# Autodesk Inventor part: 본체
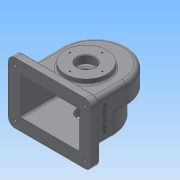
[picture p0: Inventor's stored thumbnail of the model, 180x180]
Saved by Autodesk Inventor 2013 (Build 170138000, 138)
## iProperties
Created: 2017-11
Part Number: 본체
Material: 일반
Document SubType Name: Modeling
Designer: Administrator
Density: 1 g/cm^3
Author: Administrator
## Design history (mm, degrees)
sketch "스케치1"
  geometry: L1 (-58, 0)-(-58, -80); L2 (58, 0)-(58, -80); L3 (-58, -80)-(58, -80); A1 r 58 centre (0, 0) between (58, 0) and (-58, 0); 1 further point
  constraints: 6 end point, 2 parallel, 2 point on circle, 2 tangent, 1 centre point, 1 coincident, 1 perpendicular, 1 vertical
  dimensions: "d0" = 116 diameter of A1; "d2" = 80 vertical distance of L2.end point (0, 0)
extrude "돌출1" new body sketch "스케치1" stored distance "d3" = 38; taper "d4" = 0 deg
sketch "스케치6"
  geometry: L1 (-58, -80)-(58, -80) reference; L2 (-75, -65)-(75, -65); L3 (75, -65)-(75, -80); L4 (75, -80)-(-75, -80); L5 (-75, -80)-(-75, -65); 1 further point
  constraints: 8 end point, 2 midpoint, 2 parallel, 1 horizontal, 1 perpendicular, 1 point on line
  dimensions: "d8" = 15 distance between parallel lines of L1 L2; "d9" = 150 distance between parallel lines of L3 L5
sketch "스케치7"
  geometry: L1 (58, -80)-(58, 0) reference; L2 (-58, 0)-(-58, -80) reference; L3 (-58, -80)-(58, -80) reference; L4 (-58, -23)-(-58, -80); L5 (58, -23)-(58, -80); L6 (-58, -80)-(58, -80); A1 r 58 centre (0, -23) between (58, -23) and (-58, -23); 4 further points
  constraints: 8 end point, 2 point on circle, 2 point on line, 2 tangent, 1 centre point, 1 collinear
  dimensions: "d12" = 116 diameter of A1; "d13" = 57 distance from line of L3 A1.centre; "d14" = 58 distance from line of L2 A1.centre
extrude "돌출3" join sketch "스케치7" distance "d15" = 38; taper "d16" = 0 deg
feature "쉘2" dims "d17" = 5
extrude "돌출4" join sketch "스케치6" stored distance "d18" = 110; taper "d19" = 0 deg
sketch "스케치9"
  geometry: L1 (0, 0)-(0, 110) reference; L2 (150, 0)-(0, 0) reference; L3 (150, 0)-(150, 110) reference; L4 (22, 88)-(128, 88); L5 (128, 88)-(128, 22); L6 (128, 22)-(22, 22); L7 (22, 22)-(22, 88); 1 further point
  constraints: 8 end point, 2 parallel, 1 horizontal, 1 perpendicular
  dimensions: "d24" = 66 distance between parallel lines of L6 L4; "d27" = 22 distance between parallel lines of L3 L5; "d28" = 22 distance between parallel lines of L2 L6; "d29" = 22 distance between parallel lines of L1 L7
extrude "돌출5" cut sketch "스케치9" distance "d30" = 15; taper "d31" = 0 deg
sketch "스케치10"
  geometry: L1 (-58, 0)-(-58, -65) reference; L2 (-67.459, -15)-(82.264, -15); L3 (-75, -80)-(75, -80) reference; C1 r 37.5 at (0, -15); A1 r 58 centre (0, 0) between (58, 0) and (-58, 0) reference
  constraints: 2 end point, 1 centre point, 1 perpendicular, 1 point on line, 1 vertical alignment
  dimensions: "d32" = 65 distance between parallel lines of L3 L2; "d33" = 75 diameter of C1
extrude "돌출6" join sketch "스케치10" distance "d34" = 9; taper "d35" = 0 deg
sketch "스케치11"
  geometry: C1 r 37.5 at (0, 0) reference; C2 r 16 at (0, 0); 1 further point
  constraints: 1 centre point, 1 coincident
  dimensions: "d36" = 32 diameter of C2
extrude "돌출7" cut sketch "스케치11" stored distance "d37" = 9; taper "d38" = 0 deg
sketch "스케치12"
  geometry: L1 (-58, -23)-(-58, -65) reference; L2 (-62.431, -15)-(62.431, -15); L3 (-75, -80)-(75, -80) reference; C1 r 31 at (0, -15); 2 further points
  constraints: 2 end point, 1 centre point, 1 coincident, 1 midpoint, 1 perpendicular, 1 vertical alignment
  dimensions: "d39" = 65 distance between parallel lines of L3 L2; "d40" = 62 diameter of C1
extrude "돌출8" join sketch "스케치12" distance "d41" = 10; taper "d42" = 0 deg
sketch "스케치13"
  geometry: C1 r 31 at (0, 0) reference; C2 r 16 at (0, 0); 1 further point
  constraints: 1 centre point, 1 coincident
  dimensions: "d43" = 32 diameter of C2
extrude "돌출9" cut sketch "스케치13" stored distance "d44" = 10; taper "d45" = 0 deg
fillet "모깎기1" dims "d46" = 12
node "작업 평면1"
sketch "스케치15"
  geometry: L1 (-5, 93)-(-121, 93) reference; L2 (12, 12)-(12, 98) reference; C1 r 6 at (-63, 74); 1 further point
  constraints: 1 centre point
  dimensions: "d48" = 19 distance from line of C1.centre L1; "d49" = 12 diameter of C1; "d50" = 75 distance from line of L2 C1.centre
extrude "돌출10" join sketch "스케치15" stored distance "d51" = 10; taper "d52" = 0 deg
fillet "모깎기2" dims "d53" = 3
sketch "스케치16"
  geometry: A1 r 9 centre (126, -9) between (135, -9) and (126, 0) reference; A2 r 9 centre (0, -9) between (0, 0) and (-9, -9) reference; A3 r 9 centre (0, -95) between (-9, -95) and (0, -104) reference; A4 r 9 centre (126, -95) between (126, -104) and (135, -95) reference; 5 further points
  constraints: 4 coincident
hole "구멍1" sketch "스케치16" at (126, -9), (126, -95), (0, -9), (0, -95) diameter "d54" = 5; stored, may be unused: countersink angle "d58" = 90 deg, drill point angle "d60" = 118 deg; dims "d55" = 6, "d56" = 12, "d57" = 5, "d59" = 8
sketch "스케치17" dims "d61" = 52
  geometry: C1 r 31 at (0, 0) reference; 3 further points
  constraints: 1 coincident, 1 vertical alignment, 2 other
hole "구멍2" sketch "스케치17" at (0, 26) diameter "d62" = 2.459; stored, may be unused: countersink angle "d66" = 90 deg, drill point angle "d68" = 118 deg; dims "d63" = 6, "d64" = 12, "d65" = 5, "d67" = 8
sketch "스케치18" dims "d72" = 58
  geometry: C1 r 37.5 at (0, 0) reference; 3 further points
  constraints: 1 coincident, 1 vertical alignment, 2 other
hole "구멍3" sketch "스케치18" at (0, 29) diameter "d74" = 2.459; stored, may be unused: countersink angle "d78" = 90 deg, drill point angle "d80" = 118 deg; dims "d75" = 6, "d76" = 12, "d77" = 5, "d79" = 8
hole "구멍4" diameter "d86" = 4.459; stored, may be unused: countersink angle "d90" = 90 deg, drill point angle "d92" = 118 deg; dims "d87" = 20, "d88" = 12, "d89" = 5, "d91" = 8, "d93" = 10, "d94" = 10
sketch "스케치20"
  geometry: L1 (0, -65)-(0, 0) reference; L2 (-5, -80)-(-17, -80) reference; 2 further points
  constraints: 1 other
  dimensions: "d95" = 38 distance from line of point (38, -40) L1; "d96" = 40 distance from line of L2 point (38, -40)
feature "엠보싱1" sketch "스케치20" dims "d12" = 116, "d13" = 57, "d14" = 58, "d97" = 0.5, "d98" = 0
fillet "모깎기3" dims "d99" = 3
fillet "모깎기4" dims "d100" = 3
fillet "모깎기5" dims "d101" = 8
fillet "모깎기6" dims "d102" = 3
fillet "모깎기7" dims "d103" = 3
fillet "모깎기8" dims "d104" = 3
chamfer "모따기1" distance "d105" = 1; stored, may be unused: second distance "d106" = 2, angle "d107" = 45 deg
node "솔리드1"
pattern_circular "원형 패턴1" dims angle "d70" = 360 deg
pattern_circular "원형 패턴2" dims angle "d82" = 360 deg
other parameters: "d47" = -144
